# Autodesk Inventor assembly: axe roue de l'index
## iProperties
Author: Administrateur
Created: 2001-04
Part Number: axe roue de l'index
Document SubType Name: Assemblage
Designer: Administrateur
Control State: 0
Master: False
Checked Out: False
PropertySet Name: Design Tracking Control
Shininess: 60.0
PropertySet Name: _Private Model Information
Length Units: 11269
Angle Units: 11283
Time Units: 11279
Mass Units: 11290
Length Display Precision: 3
Angle Display Precision: 2
Compacted: False
Density: 0.0
Volumn: 0.0
Area: 0.0
PropertySet Name: Model Information
